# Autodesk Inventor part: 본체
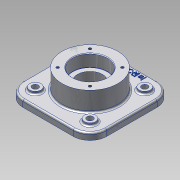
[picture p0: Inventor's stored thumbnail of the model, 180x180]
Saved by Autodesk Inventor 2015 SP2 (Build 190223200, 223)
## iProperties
Created: 2015-07
Part Number: 본체
Material: 알루미늄 6061
Document SubType Name: Modeling
Designer: AMC
Density: 2.7 g/cm^3
Appearance: 알루미늄 - 평지
Author: AMC
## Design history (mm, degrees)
sketch "스케치1"
  geometry: L1 (-75, -75)-(75, -75); L2 (75, -75)-(75, 75); L3 (75, 75)-(-75, 75); L4 (-75, 75)-(-75, -75); L5 (-75, -75)-(75, 75); L6 (75, -75)-(-75, 75); 1 further point
  constraints: 12 end point, 2 midpoint, 2 parallel, 1 horizontal, 1 perpendicular
  dimensions: "d0" = 150 distance of L3.end L2.end; "d1" = 150 distance of L2.end L1.end
extrude "돌출1" new body sketch "스케치1" distance "d2" = 12; taper "d3" = 0 deg
sketch "스케치2"
  geometry: C1 r 50 at (0, 0); 1 further point
  constraints: 1 centre point, 1 coincident
  dimensions: "d4" = 100 diameter of C1
extrude "돌출2" join sketch "스케치2" distance "d5" = 47; taper "d7" = 0 deg; dims "d6" = 23, "d8" = 0
sketch "스케치3"
  geometry: C1 r 10 at (-49, -49); C2 r 10 at (49, -49); C3 r 10 at (49, 49); C4 r 10 at (-49, 49); 1 further point
  constraints: 4 centre point, 3 equal radius, 2 horizontal alignment, 2 vertical alignment
  dimensions: "d9" = 20 diameter of C1; "d10" = 49 horizontal distance of C1.centre point (0, 0); "d11" = 98 distance of C1.centre C4.centre; "d12" = 98 distance of C2.centre C1.centre; "d13" = 49 horizontal distance of point (0, 0) C1.centre
extrude "돌출3" join sketch "스케치3" distance "d14" = 5; taper "d15" = 0 deg
fillet "모깎기1" dims "d16" = 30
hole "구멍1" diameter "d19" = 45; stored, may be unused: countersink angle "d23" = 90 deg, drill point angle "d25" = 118 deg; dims "d17" = 10, "d18" = 10, "d20" = 6, "d21" = 62, "d22" = 22, "d24" = 8
hole "구멍2" diameter "d28" = 62; stored, may be unused: countersink angle "d32" = 90 deg, drill point angle "d34" = 0 deg; dims "d26" = 10, "d27" = 10, "d29" = 6, "d30" = 62, "d31" = 22, "d33" = 22
hole "구멍3" diameter "d37" = 11; stored, may be unused: countersink angle "d41" = 90 deg, drill point angle "d43" = 118 deg; dims "d35" = 10, "d36" = 10, "d38" = 124, "d39" = 62, "d40" = 22, "d42" = 140.8
hole "구멍4" diameter "d46" = 11; stored, may be unused: countersink angle "d50" = 90 deg, drill point angle "d52" = 118 deg; dims "d44" = 10, "d45" = 10, "d47" = 124, "d48" = 62, "d49" = 22, "d51" = 140.8
hole "구멍5" diameter "d55" = 11; stored, may be unused: countersink angle "d59" = 90 deg, drill point angle "d61" = 118 deg; dims "d53" = 10, "d54" = 10, "d56" = 124, "d57" = 62, "d58" = 22, "d60" = 140.8
hole "구멍6" diameter "d64" = 11; stored, may be unused: countersink angle "d68" = 90 deg, drill point angle "d70" = 118 deg; dims "d62" = 10, "d63" = 10, "d65" = 124, "d66" = 62, "d67" = 22, "d69" = 140.8
fillet "모깎기2" dims "d71" = 3
chamfer "모따기1" distance "d72" = 1; stored, may be unused: second distance "d73" = 2, angle "d74" = 45 deg
fillet "모깎기3" dims "d75" = 0.3
sketch "스케치4"
  geometry: L1 (0, 0)-(0, 41); L2 (0, 0)-(-28.991, 28.991); A1 r 41 centre (0, 0) between (0, 41) and (-28.991, 28.991); 2 further points
  constraints: 4 end point, 2 coincident, 2 point on circle, 1 centre point, 1 vertical
  dimensions: "d76" = 82 diameter of A1; "d77" = 45 deg angle of L1 L2
hole "구멍7" sketch "스케치4" at (-28.991, 28.991) diameter "d78" = 4.917; stored, may be unused: countersink angle "d82" = 90 deg, drill point angle "d84" = 118 deg; dims "d79" = 10, "d80" = 62, "d81" = 22, "d83" = 13
sketch "스케치5"
  geometry: L1 (0, 0)-(0, -41); L2 (0, 0)-(28.991, -28.991); A1 r 41 centre (0, 0) between (0, -41) and (28.991, -28.991); 2 further points
  constraints: 4 end point, 2 coincident, 2 point on circle, 1 centre point, 1 vertical
  dimensions: "d85" = 82 diameter of A1; "d86" = 45 deg angle of L1 L2
hole "구멍8" sketch "스케치5" at (28.991, -28.991) diameter "d87" = 4.917; stored, may be unused: countersink angle "d91" = 90 deg, drill point angle "d93" = 118 deg; dims "d88" = 10, "d89" = 62, "d90" = 22, "d92" = 13
sketch "스케치6"
  geometry: 2 further points
  constraints: 1 vertical alignment, 1 other
  dimensions: "d97" = 65 distance of point (0, 0) point (0, 65)
feature "엠보싱1" sketch "스케치6" dims "d98" = 1, "d99" = 0
node "솔리드1"
pattern_circular "원형 패턴1" dims angle "d95" = 360 deg
